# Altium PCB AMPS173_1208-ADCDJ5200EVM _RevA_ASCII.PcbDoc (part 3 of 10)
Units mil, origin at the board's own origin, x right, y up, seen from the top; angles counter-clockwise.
Board outline 10500 x 2750 mil, 14 copper layers (Top Copper, Layer 2 (GND1), Layer 3 (SIG1), Layer 4 (GND2, Layer 5 (PWR1), Layer 6 (GND3), Layer 7 (PWR/SIGNAL2), Layer 8 (PWR/SIGNAL3), Layer 9 (GND4), Layer 10 PWR2), Layer 11 (GND5), Layer 12 (SIG4), Layer 13 (GND6), Bottom Copper), stack 60.6 mil thick; 701 components, 826 nets, 3386 pads, 2128 vias.
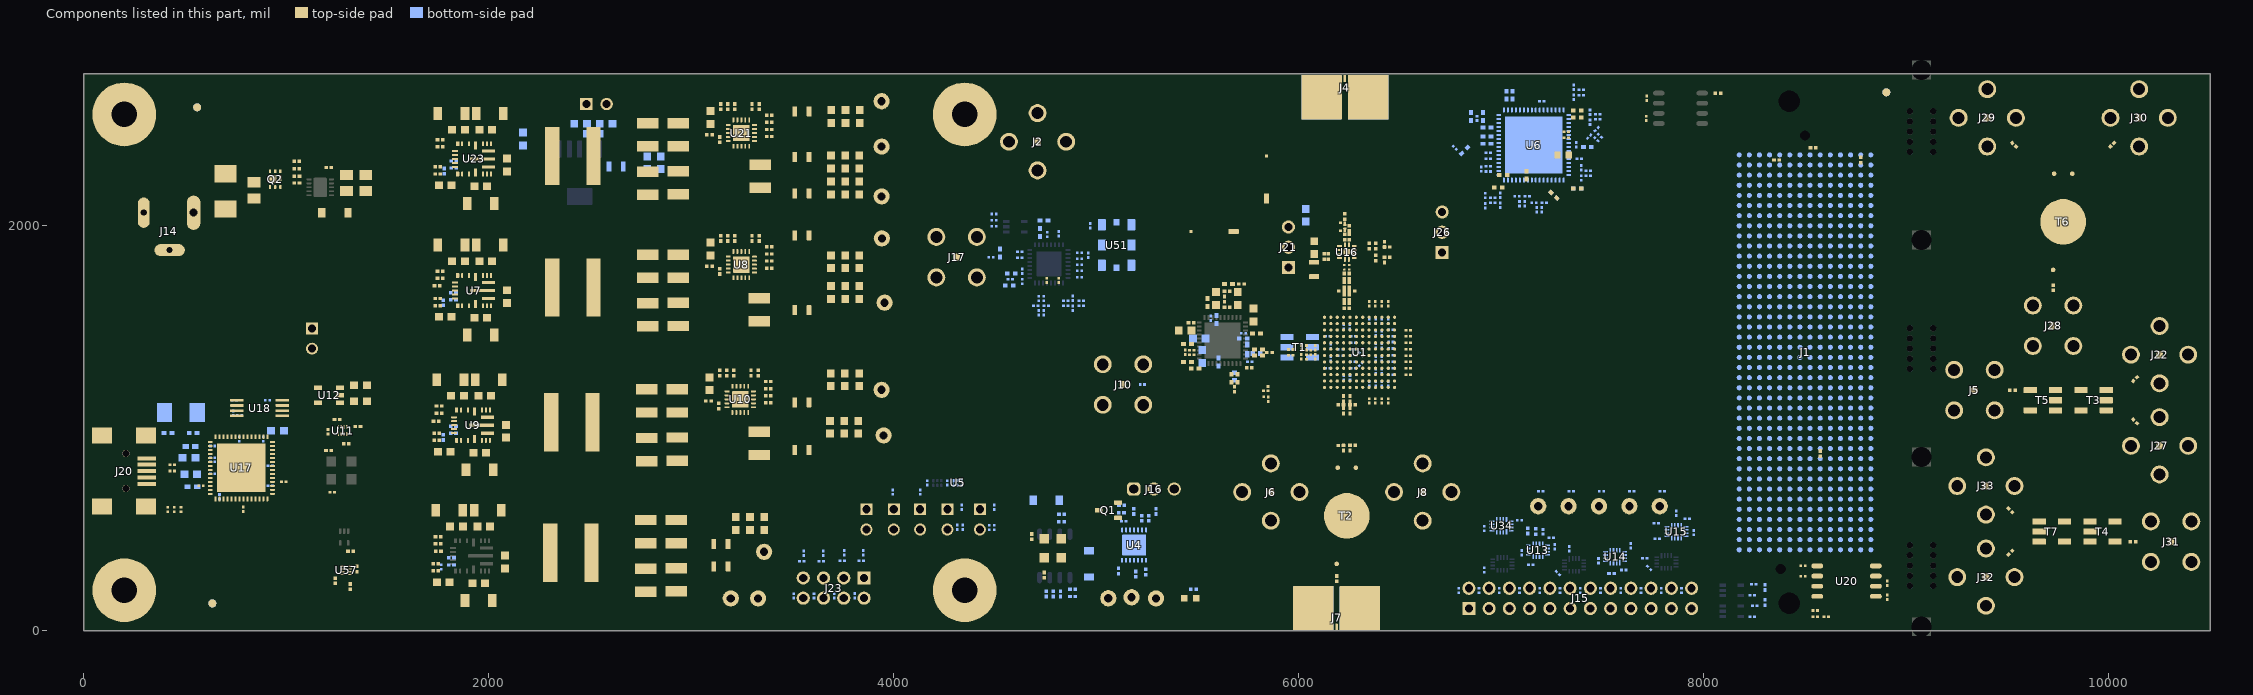
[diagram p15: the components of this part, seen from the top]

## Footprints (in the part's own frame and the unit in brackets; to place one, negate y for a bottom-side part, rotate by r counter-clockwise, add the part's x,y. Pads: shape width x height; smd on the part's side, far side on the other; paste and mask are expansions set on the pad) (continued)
Samtec_ASP-184330-01 [mil] "Terminal Array, 1.27mm, 40x14, SMT"
  round 25 smd paste-25.2: A1(-225,975) A2(-225,925) A3(-225,875) A4(-225,825) A5(-225,775) A6(-225,725) A7(-225,675) A8(-225,625) A9(-225,575) A10(-225,525) A11(-225,475) A12(-225,425) A13(-225,375) A14(-225,325) A15(-225,275) A16(-225,225) A17(-225,175) A18(-225,125) A19(-225,75) A20(-225,25) A21(-225,-25) A22(-225,-75) A23(-225,-125) A24(-225,-175) A25(-225,-225) A26(-225,-275) A27(-225,-325) A28(-225,-375) A29(-225,-425) A30(-225,-475) A31(-225,-525) A32(-225,-575) A33(-225,-625) A34(-225,-675) A35(-225,-725) A36(-225,-775) A37(-225,-825) A38(-225,-875) A39(-225,-925) A40(-225,-975) B1(-175,975) B2(-175,925) B3(-175,875) B4(-175,825) B5(-175,775) B6(-175,725) B7(-175,675) B8(-175,625) B9(-175,575) B10(-175,525) B11(-175,475) B12(-175,425) B13(-175,375) B14(-175,325) B15(-175,275) B16(-175,225) B17(-175,175) B18(-175,125) B19(-175,75) B20(-175,25) B21(-175,-25) B22(-175,-75) B23(-175,-125) B24(-175,-175) B25(-175,-225) B26(-175,-275) B27(-175,-325) B28(-175,-375) B29(-175,-425) B30(-175,-475) B31(-175,-525) B32(-175,-575) B33(-175,-625) B34(-175,-675) B35(-175,-725) B36(-175,-775) B37(-175,-825) B38(-175,-875) B39(-175,-925) B40(-175,-975) C1(-125,975) C2(-125,925) C3(-125,875) C4(-125,825) C5(-125,775) C6(-125,725) C7(-125,675) C8(-125,625) C9(-125,575) C10(-125,525) C11(-125,475) C12(-125,425) C13(-125,375) C14(-125,325) C15(-125,275) C16(-125,225) C17(-125,175) C18(-125,125) C19(-125,75) C20(-125,25) C21(-125,-25) C22(-125,-75) C23(-125,-125) C24(-125,-175) C25(-125,-225) C26(-125,-275) C27(-125,-325) C28(-125,-375) C29(-125,-425) C30(-125,-475) C31(-125,-525) C32(-125,-575) C33(-125,-625) C34(-125,-675) C35(-125,-725) C36(-125,-775) C37(-125,-825) C38(-125,-875) C39(-125,-925) C40(-125,-975) D1(-75,975) D2(-75,925) D3(-75,875) D4(-75,825) D5(-75,775) D6(-75,725) D7(-75,675) D8(-75,625) D9(-75,575) D10(-75,525) D11(-75,475) D12(-75,425) D13(-75,375) D14(-75,325) D15(-75,275) D16(-75,225) D17(-75,175) D18(-75,125) D19(-75,75) D20(-75,25) D21(-75,-25) D22(-75,-75) D23(-75,-125) D24(-75,-175) D25(-75,-225) D26(-75,-275) D27(-75,-325) D28(-75,-375) D29(-75,-425) D30(-75,-475) D31(-75,-525) D32(-75,-575) D33(-75,-625) D34(-75,-675) D35(-75,-725) D36(-75,-775) D37(-75,-825) D38(-75,-875) D39(-75,-925) D40(-75,-975) E1(-25,975) E2(-25,925) E3(-25,875) E4(-25,825) E5(-25,775) E6(-25,725) E7(-25,675) E8(-25,625) E9(-25,575) E10(-25,525) E11(-25,475) E12(-25,425) E13(-25,375) E14(-25,325) E15(-25,275) E16(-25,225) E17(-25,175) E18(-25,125) E19(-25,75) E20(-25,25) E21(-25,-25) E22(-25,-75) E23(-25,-125) E24(-25,-175) E25(-25,-225) E26(-25,-275) E27(-25,-325) E28(-25,-375) E29(-25,-425) E30(-25,-475) E31(-25,-525) E32(-25,-575) E33(-25,-625) E34(-25,-675) E35(-25,-725) E36(-25,-775) E37(-25,-825) E38(-25,-875) E39(-25,-925) E40(-25,-975) F1(25,975) F2(25,925) F3(25,875) F4(25,825) F5(25,775) F6(25,725) F7(25,675) F8(25,625) F9(25,575) F10(25,525) F11(25,475) F12(25,425) F13(25,375) F14(25,325) F15(25,275) F16(25,225) F17(25,175) F18(25,125) F19(25,75) F20(25,25) F21(25,-25) F22(25,-75) F23(25,-125) F24(25,-175) F25(25,-225) F26(25,-275) F27(25,-325) F28(25,-375) F29(25,-425) F30(25,-475) F31(25,-525) F32(25,-575) F33(25,-625) F34(25,-675) F35(25,-725) F36(25,-775) F37(25,-825) F38(25,-875) F39(25,-925) F40(25,-975) G1(75,975) G2(75,925) G3(75,875) G4(75,825) G5(75,775) G6(75,725) G7(75,675) G8(75,625) G9(75,575) G10(75,525) G11(75,475) G12(75,425) G13(75,375) G14(75,325) G15(75,275) G16(75,225) G17(75,175) G18(75,125) G19(75,75) G20(75,25) G21(75,-25) G22(75,-75) G23(75,-125) G24(75,-175) G25(75,-225) G26(75,-275) G27(75,-325) G28(75,-375) G29(75,-425) G30(75,-475) G31(75,-525) G32(75,-575) G33(75,-625) G34(75,-675) G35(75,-725) G36(75,-775) G37(75,-825) G38(75,-875) G39(75,-925) G40(75,-975) H1(125,975) H2(125,925) H3(125,875) H4(125,825) H5(125,775) H6(125,725) H7(125,675) H8(125,625) H9(125,575) H10(125,525) H11(125,475) H12(125,425) H13(125,375) H14(125,325) H15(125,275) H16(125,225) H17(125,175) H18(125,125) H19(125,75) H20(125,25) H21(125,-25) H22(125,-75) H23(125,-125) H24(125,-175) H25(125,-225) H26(125,-275) H27(125,-325) H28(125,-375) H29(125,-425) H30(125,-475) H31(125,-525) H32(125,-575) H33(125,-625) H34(125,-675) H35(125,-725) H36(125,-775) H37(125,-825) H38(125,-875) H39(125,-925) H40(125,-975) J1(175,975) J2(175,925) J3(175,875) J4(175,825) J5(175,775) J6(175,725) J7(175,675) J8(175,625) J9(175,575) J10(175,525) J11(175,475) J12(175,425) J13(175,375) J14(175,325) J15(175,275) J16(175,225) J17(175,175) J18(175,125) J19(175,75) J20(175,25) J21(175,-25) J22(175,-75) J23(175,-125) J24(175,-175) J25(175,-225) J26(175,-275) J27(175,-325) J28(175,-375) J29(175,-425) J30(175,-475) J31(175,-525) J32(175,-575) J33(175,-625) J34(175,-675) J35(175,-725) J36(175,-775) J37(175,-825) J38(175,-875) J39(175,-925) J40(175,-975) K1(225,975) K2(225,925) K3(225,875) K4(225,825) K5(225,775) K6(225,725) K7(225,675) K8(225,625) K9(225,575) K10(225,525) K11(225,475) K12(225,425) K13(225,375) K14(225,325) K15(225,275) K16(225,225) K17(225,175) K18(225,125) K19(225,75) K20(225,25) K21(225,-25) K22(225,-75) K23(225,-125) K24(225,-175) K25(225,-225) K26(225,-275) K27(225,-325) K28(225,-375) K29(225,-425) K30(225,-475) K31(225,-525) K32(225,-575) K33(225,-625) K34(225,-675) K35(225,-725) K36(225,-775) K37(225,-825) K38(225,-875) K39(225,-925) K40(225,-975) L1(275,975) L2(275,925) L3(275,875) L4(275,825) L5(275,775) L6(275,725) L7(275,675) L8(275,625) L9(275,575) L10(275,525) L11(275,475) L12(275,425) L13(275,375) L14(275,325) L15(275,275) L16(275,225) L17(275,175) L18(275,125) L19(275,75) L20(275,25) L21(275,-25) L22(275,-75) L23(275,-125) L24(275,-175) L25(275,-225) L26(275,-275) L27(275,-325) L28(275,-375) L29(275,-425) L30(275,-475) L31(275,-525) L32(275,-575) L33(275,-625) L34(275,-675) L35(275,-725) L36(275,-775) L37(275,-825) L38(275,-875) L39(275,-925) L40(275,-975) M1(325,975) M2(325,925) M3(325,875) M4(325,825) M5(325,775) M6(325,725) M7(325,675) M8(325,625) M9(325,575) M10(325,525) M11(325,475) M12(325,425) M13(325,375) M14(325,325) M15(325,275) M16(325,225) M17(325,175) M18(325,125) M19(325,75) M20(325,25) M21(325,-25) M22(325,-75) M23(325,-125) M24(325,-175) M25(325,-225) M26(325,-275) M27(325,-325) M28(325,-375) M29(325,-425) M30(325,-475) M31(325,-525) M32(325,-575) M33(325,-625) M34(325,-675) M35(325,-725) M36(325,-775) M37(325,-825) M38(325,-875) M39(325,-925) M40(325,-975) Y1(-325,975) Y2(-325,925) Y3(-325,875) Y4(-325,825) Y5(-325,775) Y6(-325,725) Y7(-325,675) Y8(-325,625) Y9(-325,575) Y10(-325,525) Y11(-325,475) Y12(-325,425) Y13(-325,375) Y14(-325,325) Y15(-325,275) Y16(-325,225) Y17(-325,175) Y18(-325,125) Y19(-325,75) Y20(-325,25) Y21(-325,-25) Y22(-325,-75) Y23(-325,-125) Y24(-325,-175) Y25(-325,-225) Y26(-325,-275) Y27(-325,-325) Y28(-325,-375) Y29(-325,-425) Y30(-325,-475) Y31(-325,-525) Y32(-325,-575) Y33(-325,-625) Y34(-325,-675) Y35(-325,-725) Y36(-325,-775) Y37(-325,-825) Y38(-325,-875) Y39(-325,-925) Y40(-325,-975) Z1(-275,975) Z2(-275,925) Z3(-275,875) Z4(-275,825) Z5(-275,775) Z6(-275,725) Z7(-275,675) Z8(-275,625) Z9(-275,575) Z10(-275,525) Z11(-275,475) Z12(-275,425) Z13(-275,375) Z14(-275,325) Z15(-275,275) Z16(-275,225) Z17(-275,175) Z18(-275,125) Z19(-275,75) Z20(-275,25) Z21(-275,-25) Z22(-275,-75) Z23(-275,-125) Z24(-275,-175) Z25(-275,-225) Z26(-275,-275) Z27(-275,-325) Z28(-275,-375) Z29(-275,-425) Z30(-275,-475) Z31(-275,-525) Z32(-275,-575) Z33(-275,-625) Z34(-275,-675) Z35(-275,-725) Z36(-275,-775) Z37(-275,-825) Z38(-275,-875) Z39(-275,-925) Z40(-275,-975)
  round 35 on Bottom Paste: ""(-325,-975) ""(-325,-925) ""(-325,-875) ""(-325,-825) ""(-325,-775) ""(-325,-725) ""(-325,-675) ""(-325,-625) ""(-325,-575) ""(-325,-525) ""(-325,-475) ""(-325,-425) ""(-325,-375) ""(-325,-325) ""(-325,-275) ""(-325,-225) ""(-325,-175) ""(-325,-125) ""(-325,-75) ""(-325,-25) ""(-325,25) ""(-325,75) ""(-325,125) ""(-325,175) ""(-325,225) ""(-325,275) ""(-325,325) ""(-325,375) ""(-325,425) ""(-325,475) ""(-325,525) ""(-325,575) ""(-325,625) ""(-325,675) ""(-325,725) ""(-325,775) ""(-325,825) ""(-325,875) ""(-325,925) ""(-325,975) ""(-275,-975) ""(-275,-925) ""(-275,-875) ""(-275,-825) ""(-275,-775) ""(-275,-725) ""(-275,-675) ""(-275,-625) ""(-275,-575) ""(-275,-525) ""(-275,-475) ""(-275,-425) ""(-275,-375) ""(-275,-325) ""(-275,-275) ""(-275,-225) ""(-275,-175) ""(-275,-125) ""(-275,-75) ""(-275,-25) ""(-275,25) ""(-275,75) ""(-275,125) ""(-275,175) ""(-275,225) ""(-275,275) ""(-275,325) ""(-275,375) ""(-275,425) ""(-275,475) ""(-275,525) ""(-275,575) ""(-275,625) ""(-275,675) ""(-275,725) ""(-275,775) ""(-275,825) ""(-275,875) ""(-275,925) ""(-275,975) ""(-225,-975) ""(-225,-925) ""(-225,-875) ""(-225,-825) ""(-225,-775) ""(-225,-725) ""(-225,-675) ""(-225,-625) ""(-225,-575) ""(-225,-525) ""(-225,-475) ""(-225,-425) ""(-225,-375) ""(-225,-325) ""(-225,-275) ""(-225,-225) ""(-225,-175) ""(-225,-125) ""(-225,-75) ""(-225,-25) ""(-225,25) ""(-225,75) ""(-225,125) ""(-225,175) ""(-225,225) ""(-225,275) ""(-225,325) ""(-225,375) ""(-225,425) ""(-225,475) ""(-225,525) ""(-225,575) ""(-225,625) ""(-225,675) ""(-225,725) ""(-225,775) ""(-225,825) ""(-225,875) ""(-225,925) ""(-225,975) ""(-175,-975) ""(-175,-925) ""(-175,-875) ""(-175,-825) ""(-175,-775) ""(-175,-725) ""(-175,-675) ""(-175,-625) ""(-175,-575) ""(-175,-525) ""(-175,-475) ""(-175,-425) ""(-175,-375) ""(-175,-325) ""(-175,-275) ""(-175,-225) ""(-175,-175) ""(-175,-125) ""(-175,-75) ""(-175,-25) ""(-175,25) ""(-175,75) ""(-175,125) ""(-175,175) ""(-175,225) ""(-175,275) ""(-175,325) ""(-175,375) ""(-175,425) ""(-175,475) ""(-175,525) ""(-175,575) ""(-175,625) ""(-175,675) ""(-175,725) ""(-175,775) ""(-175,825) ""(-175,875) ""(-175,925) ""(-175,975) ""(-125,-975) ""(-125,-925) ""(-125,-875) ""(-125,-825) ""(-125,-775) ""(-125,-725) ""(-125,-675) ""(-125,-625) ""(-125,-575) ""(-125,-525) ""(-125,-475) ""(-125,-425) ""(-125,-375) ""(-125,-325) ""(-125,-275) ""(-125,-225) ""(-125,-175) ""(-125,-125) ""(-125,-75) ""(-125,-25) ""(-125,25) ""(-125,75) ""(-125,125) ""(-125,175) ""(-125,225) ""(-125,275) ""(-125,325) ""(-125,375) ""(-125,425) ""(-125,475) ""(-125,525) ""(-125,575) ""(-125,625) ""(-125,675) ""(-125,725) ""(-125,775) ""(-125,825) ""(-125,875) ""(-125,925) ""(-125,975) ""(-75,-975) ""(-75,-925) ""(-75,-875) ""(-75,-825) ""(-75,-775) ""(-75,-725) ""(-75,-675) ""(-75,-625) ""(-75,-575) ""(-75,-525) ""(-75,-475) ""(-75,-425) ""(-75,-375) ""(-75,-325) ""(-75,-275) ""(-75,-225) ""(-75,-175) ""(-75,-125) ""(-75,-75) ""(-75,-25) ""(-75,25) ""(-75,75) ""(-75,125) ""(-75,175) ""(-75,225) ""(-75,275) ""(-75,325) ""(-75,375) ""(-75,425) ""(-75,475) ""(-75,525) ""(-75,575) ""(-75,625) ""(-75,675) ""(-75,725) ""(-75,775) ""(-75,825) ""(-75,875) ""(-75,925) ""(-75,975) ""(-25,-975) ""(-25,-925) ""(-25,-875) ""(-25,-825) ""(-25,-775) ""(-25,-725) ""(-25,-675) ""(-25,-625) ""(-25,-575) ""(-25,-525) ""(-25,-475) ""(-25,-425) ""(-25,-375) ""(-25,-325) ""(-25,-275) ""(-25,-225) ""(-25,-175) ""(-25,-125) ""(-25,-75) ""(-25,-25) ""(-25,25) ""(-25,75) ""(-25,125) ""(-25,175) ""(-25,225) ""(-25,275) ""(-25,325) ""(-25,375) ""(-25,425) ""(-25,475) ""(-25,525) ""(-25,575) ""(-25,625) ""(-25,675) ""(-25,725) ""(-25,775) ""(-25,825) ""(-25,875) ""(-25,925) ""(-25,975) ""(25,-975) ""(25,-925) ""(25,-875) ""(25,-825) ""(25,-775) ""(25,-725) ""(25,-675) ""(25,-625) ""(25,-575) ""(25,-525) ""(25,-475) ""(25,-425) ""(25,-375) ""(25,-325) ""(25,-275) ""(25,-225) ""(25,-175) ""(25,-125) ""(25,-75) ""(25,-25) ""(25,25) ""(25,75) ""(25,125) ""(25,175) ""(25,225) ""(25,275) ""(25,325) ""(25,375) ""(25,425) ""(25,475) ""(25,525) ""(25,575) ""(25,625) ""(25,675) ""(25,725) ""(25,775) ""(25,825) ""(25,875) ""(25,925) ""(25,975) ""(75,-975) ""(75,-925) ""(75,-875) ""(75,-825) ""(75,-775) ""(75,-725) ""(75,-675) ""(75,-625) ""(75,-575) ""(75,-525) ""(75,-475) ""(75,-425) ""(75,-375) ""(75,-325) ""(75,-275) ""(75,-225) ""(75,-175) ""(75,-125) ""(75,-75) ""(75,-25) ""(75,25) ""(75,75) ""(75,125) ""(75,175) ""(75,225) ""(75,275) ""(75,325) ""(75,375) ""(75,425) ""(75,475) ""(75,525) ""(75,575) ""(75,625) ""(75,675) ""(75,725) ""(75,775) ""(75,825) ""(75,875) ""(75,925) ""(75,975) ""(125,-975) ""(125,-925) ""(125,-875) ""(125,-825) ""(125,-775) ""(125,-725) ""(125,-675) ""(125,-625) ""(125,-575) ""(125,-525) ""(125,-475) ""(125,-425) ""(125,-375) ""(125,-325) ""(125,-275) ""(125,-225) ""(125,-175) ""(125,-125) ""(125,-75) ""(125,-25) ""(125,25) ""(125,75) ""(125,125) ""(125,175) ""(125,225) ""(125,275) ""(125,325) ""(125,375) ""(125,425) ""(125,475) ""(125,525) ""(125,575) ""(125,625) ""(125,675) ""(125,725) ""(125,775) ""(125,825) ""(125,875) ""(125,925) ""(125,975) ""(175,-975) ""(175,-925) ""(175,-875) ""(175,-825) ""(175,-775) ""(175,-725) ""(175,-675) ""(175,-625) ""(175,-575) ""(175,-525) ""(175,-475) ""(175,-425) ""(175,-375) ""(175,-325) ""(175,-275) ""(175,-225) ""(175,-175) ""(175,-125) ""(175,-75) ""(175,-25) ""(175,25) ""(175,75) ""(175,125) ""(175,175) ""(175,225) ""(175,275) ""(175,325) ""(175,375) ""(175,425) ""(175,475) ""(175,525) ""(175,575) ""(175,625) ""(175,675) ""(175,725) ""(175,775) ""(175,825) ""(175,875) ""(175,925) ""(175,975) ""(225,-975) ""(225,-925) ""(225,-875) ""(225,-825) ""(225,-775) ""(225,-725) ""(225,-675) ""(225,-625) ""(225,-575) ""(225,-525) ""(225,-475) ""(225,-425) ""(225,-375) ""(225,-325) ""(225,-275) ""(225,-225) ""(225,-175) ""(225,-125) ""(225,-75) ""(225,-25) ""(225,25) ""(225,75) ""(225,125) ""(225,175) ""(225,225) ""(225,275) ""(225,325) ""(225,375) ""(225,425) ""(225,475) ""(225,525) ""(225,575) ""(225,625) ""(225,675) ""(225,725) ""(225,775) ""(225,825) ""(225,875) ""(225,925) ""(225,975) ""(275,-975) ""(275,-925) ""(275,-875) ""(275,-825) ""(275,-775) ""(275,-725) ""(275,-675) ""(275,-625) ""(275,-575) ""(275,-525) ""(275,-475) ""(275,-425) ""(275,-375) ""(275,-325) ""(275,-275) ""(275,-225) ""(275,-175) ""(275,-125) ""(275,-75) ""(275,-25) ""(275,25) ""(275,75) ""(275,125) ""(275,175) ""(275,225) ""(275,275) ""(275,325) ""(275,375) ""(275,425) ""(275,475) ""(275,525) ""(275,575) ""(275,625) ""(275,675) ""(275,725) ""(275,775) ""(275,825) ""(275,875) ""(275,925) ""(275,975) ""(325,-975) ""(325,-925) ""(325,-875) ""(325,-825) ""(325,-775) ""(325,-725) ""(325,-675) ""(325,-625) ""(325,-575) ""(325,-525) ""(325,-475) ""(325,-425) ""(325,-375) ""(325,-325) ""(325,-275) ""(325,-225) ""(325,-175) ""(325,-125) ""(325,-75) ""(325,-25) ""(325,25) ""(325,75) ""(325,125) ""(325,175) ""(325,225) ""(325,275) ""(325,325) ""(325,375) ""(325,425) ""(325,475) ""(325,525) ""(325,575) ""(325,625) ""(325,675) ""(325,725) ""(325,775) ""(325,825) ""(325,875) ""(325,925) ""(325,975)
  round 0 hole 50 unplated: ""(0,1070.5) ""(120,-1070.5)
  silkscreen extent -405,-1098 389,1133, body extent -389,-1098 389,1133, height 289
SIA0008B [mm] "SIP 8-Leads, Body 5x7mm"
  rrect10% 1x1.4 smd paste-0.5: 1(-1.85,2.54) 2(-1.85,0) 3(-1.85,-2.54) 4(1.85,-2.54) 5(1.85,0) 6(1.85,2.54)
  rrect0% 1x0.6 on Bottom Paste: 1_1(-1.85,2.14) 1_2(-1.85,2.94) 2_1(-1.85,-0.4) 2_2(-1.85,0.4) 3_1(-1.85,-2.14) 3_2(-1.85,-2.94) 4_1(1.85,-2.14) 4_2(1.85,-2.94) 5_1(1.85,-0.4) 5_2(1.85,0.4) 6_1(1.85,2.94) 6_2(1.85,2.14)
  rrect12% 0.8x0.8 smd: 7(0,2.865) 8(0,-2.865)
  silkscreen extent -2.64,-3.63 2.64,3.63, body extent -2.56,-3.56 2.56,3.56, height 1.13
SMB-Bi [mil] "Molded Diode, 2-Leads, Body 5.4x3.6mm, IPC Medium Density, based on OnSemi component dimensions"
  rect 85x107.99 smd: 1(-87.01,0) 2(87.01,0)
  silkscreen extent -125,-79 125,79, body extent -104,-73 104,73, height 89
SOD-123 [mm] "On Semi recommended land pattern"
  rect 0.915x1.22 smd: 1(-1.637,0) 2(1.637,0)
  silkscreen extent -2.74,-1.17 2.03,1.17, body extent -1.93,-0.9 1.93,0.9, height 1.35
SOIC127P800X216-8N [mm] "SOIC, 8-Leads, Body 5.3x5.3mm (max), Pitch 1.27mm, IPC Medium Density"
  oval 1.5x0.6 smd: 1(-3.675,1.905) 2(-3.675,0.635) 3(-3.675,-0.635) 4(-3.675,-1.905) 5(3.675,-1.905) 6(3.675,-0.635) 7(3.675,0.635) 8(3.675,1.905)
  silkscreen extent -4.11,-2.7 2.69,2.7, body extent -4.1,-2.7 4.1,2.7, height 2.17
SOT-23 [mm] "SOT23, 3-Leads, Body 2.9x1.3mm, Pitch 0.95mm, Lead Span 2.5mm, IPC Medium Density"
  rrect50% 1x0.6 smd: 1(-1.2,0.95) 2(-1.2,-0.95) 3(1.2,0)
  silkscreen extent -1.62,-1.5 0.7,1.5, body extent -1.16,-1.45 1.21,1.45, height 1
TI_Stacked_Overlay_Small [mil]
  silkscreen extent -418,-98 418,98
TSSOP-8 [mm] "TSSOP, 8-Leads, Body 3.1x4.5mm (max), Pitch 0.65mm, IPC Medium Density"
  rrect50% 1.7x0.35 smd: 1(-2.85,0.975) 2(-2.85,0.325) 3(-2.85,-0.325) 4(-2.85,-0.975) 5(2.85,-0.975) 6(2.85,-0.325) 7(2.85,0.325) 8(2.85,0.975)
  silkscreen extent -2.97,-1.55 1.6,1.82, body extent -3.2,-1.55 3.2,1.55, height 1.07
TSW-104-07-G-D [mm] "Samtec 100mil, 2x4, 230 mil above insulator"
  rrect6% 1.65x1.65 hole 1.016: 1(-3.81,-1.27)
  round 1.65 hole 1.016: 2(-3.81,1.27) 3(-1.27,-1.27) 4(-1.27,1.27) 5(1.27,-1.27) 6(1.27,1.27) 7(3.81,-1.27) 8(3.81,1.27)
  silkscreen extent -6.11,-2.54 5.08,2.54, body extent -5.08,-2.54 5.08,2.54, height 8.38
TSW-112-07-G-D [mm] "Samtec 100mil, 2x12, 230 mil above insulator"
  rrect6% 1.65x1.65 hole 1.016: 1(-13.97,-1.27)
  round 1.65 hole 1.016: 2(-13.97,1.27) 3(-11.43,-1.27) 4(-11.43,1.27) 5(-8.89,-1.27) 6(-8.89,1.27) 7(-6.35,-1.27) 8(-6.35,1.27) 9(-3.81,-1.27) 10(-3.81,1.27) 11(-1.27,-1.27) 12(-1.27,1.27) 13(1.27,-1.27) 14(1.27,1.27) 15(3.81,-1.27) 16(3.81,1.27) 17(6.35,-1.27) 18(6.35,1.27) 19(8.89,-1.27) 20(8.89,1.27) 21(11.43,-1.27) 22(11.43,1.27) 23(13.97,-1.27) 24(13.97,1.27)
  silkscreen extent -16.26,-2.54 15.24,2.54, body extent -15.24,-2.54 15.24,2.54, height 8.38
VQFN-56 [mm] "VQFN, 56-Leads, Body 8x8mm, Pitch 0.5mm"
  rrect40% 0.6x0.25 smd: 1(-3.9,3.25) 2(-3.9,2.75) 3(-3.9,2.25) 4(-3.9,1.75) 5(-3.9,1.25) 6(-3.9,0.75) 7(-3.9,0.25) 8(-3.9,-0.25) 9(-3.9,-0.75) 10(-3.9,-1.25) 11(-3.9,-1.75) 12(-3.9,-2.25) 13(-3.9,-2.75) 14(-3.9,-3.25) 29(3.9,-3.25) 30(3.9,-2.75) 31(3.9,-2.25) 32(3.9,-1.75) 33(3.9,-1.25) 34(3.9,-0.75) 35(3.9,-0.25) 36(3.9,0.25) 37(3.9,0.75) 38(3.9,1.25) 39(3.9,1.75) 40(3.9,2.25) 41(3.9,2.75) 42(3.9,3.25)
  rrect40% 0.25x0.6 smd: 15(-3.25,-3.9) 16(-2.75,-3.9) 17(-2.25,-3.9) 18(-1.75,-3.9) 19(-1.25,-3.9) 20(-0.75,-3.9) 21(-0.25,-3.9) 22(0.25,-3.9) 23(0.75,-3.9) 24(1.25,-3.9) 25(1.75,-3.9) 26(2.25,-3.9) 27(2.75,-3.9) 28(3.25,-3.9) 43(3.25,3.9) 44(2.75,3.9) 45(2.25,3.9) 46(1.75,3.9) 47(1.25,3.9) 48(0.75,3.9) 49(0.25,3.9) 50(-0.25,3.9) 51(-0.75,3.9) 52(-1.25,3.9) 53(-1.75,3.9) 54(-2.25,3.9) 55(-2.75,3.9) 56(-3.25,3.9)
  rect 6.1x6.1 smd paste-6.1: 57(0,0)
  rect 0.973x0.973 on Top Paste: ""(-2.346,-2.346) ""(-2.346,-1.173) ""(-2.346,0) ""(-2.346,1.173) ""(-2.346,2.346) ""(-1.173,-2.346) ""(-1.173,-1.173) ""(-1.173,0) ""(-1.173,1.173) ""(-1.173,2.346) ""(0,-2.346) ""(0,-1.173) ""(0,0) ""(0,1.173) ""(0,2.346) ""(1.173,-2.346) ""(1.173,-1.173) ""(1.173,0) ""(1.173,1.173) ""(1.173,2.346) ""(2.346,-2.346) ""(2.346,-1.173) ""(2.346,0) ""(2.346,1.173) ""(2.346,2.346)
  body extent -4.04,-4.04 4.04,4.04, height 1
WEEE_Minimum [mil] "WEEElie bin"
  silkscreen extent -95,-172 99,104
WURTH_61300311121 [mm] "Header, 2.54mm, 3x1, TH"
  rrect50% 1.65x1.65 hole 1.15: 1(-2.54,0)
  round 1.65 hole 1.15: 2(0,0) 3(2.54,0)
  body extent -3.81,-1.27 3.81,1.27, height 8.54
XAL8080 [mm] "Coilcraft"
  rect 1.78x7.31 smd: 1(-2.58,0) 2(2.58,0)
  silkscreen extent -4.2,-4.45 4.2,4.45, body extent -4.15,-4.4 4.15,4.4, height 8
XTAL_ABM3 [mm] "Abracon recommended land pattern 12.28.10"
  rect 1.9x2.4 smd: 1(-2.05,0) 2(2.05,0)
  silkscreen extent -2.67,-1.78 2.67,1.78, body extent -2.6,-1.7 2.6,1.7, height 1.3

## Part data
C1 C2 C3 C6 C13 C14 C15 C16 C17 C18 C19 C20 C21 C22 C23 C24 C25 C26 C27 C28 C29 C30 C31 C32 C33 C34 C35 C36 C37 C38 C39 C40 C41 C42 C43 C44 C45 C46 C49 C50 C52 C60 C61 C73 C74 C75 C90 C91 C93 C98 C99 C105 C107 C108 C285 C306 C319 C320 C321 C322 C346 C347 C417 C421 C422 C423 C424 C425 C426 C427 C428 C429 C430 C431 C432 C433 C505 C506 C507 C508: library part CMP-0860981-1, "CAP, CERM, 0.1 µF, 16 V,+/- 10%, X7R, 0201", Cap_Case=0201, Manufacturer="Passive Plus", TempCo=X7R, Tolerance_%=10%, Value2=16V, ValueDisplayed=0.1µF
C4 C5 C324 C333 C415 C416: library part CMP-0009632-3, "CAP, CERM, 100 pF, 25 V, +/- 5%, C0G/NP0, 0201", Cap_Case=0201, Manufacturer=TDK, Supplier Part Number 1=445-4675-1-ND, TempCo=C0G/NP0, Tolerance_%=5%, Value1=Unknown, Value2=25V, ValueDisplayed=100pF
C7 C8 C9 C10 C11 C12 C101 C102 C103 C104 C135 C190 C215 C216 C217 C218 C243 C244 C245: library part CMP-0009220-2, "CAP, CERM, 47 uF, 10 V, +/- 10%, X7R, 1210", Cap_Case=1210, Manufacturer=MuRata, Supplier Part Number 1=490-5312-1-ND, TempCo=X7R, Tolerance_%=10%, Value1=Unknown, Value2=10V, ValueDisplayed=47uF
C47 C53 C54 C55 C56 C57 C58 C315 C316 C326 C331 C332 C334 C335 C339 C341 C344: library part CMP-0064947-2, "CAP, CERM, 1 uF, 6.3 V,+/- 10%, X7R, 0402", Cap_Case=0402, Manufacturer=MuRata, Supplier Part Number 1=490-10024-1-ND, TempCo=X7R, Tolerance_%=10%, Value1=Unknown, Value2=6.3V, ValueDisplayed=1uF
C48 C51 C59 C65 C76 C77 C78 C79 C81 C82 C84 C86 C89 C92 C94 C95 C96 C115 C124 C125 C126 C136 C156 C157 C158 C159 C160 C161 C162 C163 C167 C168 C169 C170 C171 C172 C173 C174 C175 C176 C178 C179 C180 C181 C182 C183 C192 C204 C207 C220 C287 C288 C290 C325 C329 C330 C359 C360 C405: library part CMP-0064970-1, "CAP, CERM, 0.1 uF, 16 V,+/- 10%, X7R, 0201", Cap_Case=0201, Manufacturer=MuRata, Supplier Part Number 1=81-GRM033Z71C104KE4D, TempCo=X7R, Tolerance_%=10%, Value1=Unknown, Value2=16V, ValueDisplayed=0.1uF
C62 C63 C64 C66 C97 C109 C110 C111 C112 C113 C139 C140 C141 C142 C145 C146 C147 C195 C201 C202 C203 C223 C224 C225 C226 C229 C230 C231 C307 C308 C309 C327 C328 C340 C342 C343 C345: library part CMP-0007497-5, "CAP, CERM, 10 uF, 10 V, +/- 20%, X7R, 0603", Cap_Case=0603, Manufacturer=MuRata, Supplier Part Number 1=81-GRM188Z71A106MA3D, TempCo=X7R, Tolerance_%=20%, Value1=Unknown, Value2=10V, ValueDisplayed=10uF
C67 C129 C165 C208: library part CMP-0007424-4, "CAP, CERM, 0.47 uF, 25 V, +/- 10%, X7R, 0603", Cap_Case=0603, Manufacturer=MuRata, Supplier Part Number 1=490-3291-1-ND, TempCo=X7R, Tolerance_%=10%, Value1=Unknown, Value2=25V, ValueDisplayed=0.47uF
C68 C69 C70 C128 C130 C131 C184 C185 C186 C209 C210 C211: library part CMP-0008705-2, "CAP, CERM, 10 uF, 35 V, +/- 10%, X7R, 1206", Cap_Case=1206_180, Manufacturer=TDK, Supplier Part Number 1=445-14799-1-ND, TempCo=X7R, Tolerance_%=10%, Value1="0.002229 ohm", Value2=35V, ValueDisplayed=10uF
C71 C72 C100 C114 C132 C133 C134 C187 C188 C189 C205 C212 C213 C214: library part CMP-0007039-5, "CAP, CERM, 0.1 uF, 25 V, +/- 10%, X7R, 0603", Cap_Case=0603, Manufacturer=TDK, Supplier Part Number 1=445-1316-1-ND, TempCo=X7R, Tolerance_%=10%, Value1=Unknown, Value2=25V, ValueDisplayed=0.1uF
C80: library part CMP-0007008-5, "CAP, CERM, 3.3 uF, 25 V, +/- 10%, X5R, 0603", Cap_Case=0603, Manufacturer=TDK, Supplier Part Number 1=445-14141-1-ND, TempCo=X5R, Tolerance_%=10%, Value1=Unknown, Value2=25V, ValueDisplayed=3.3uF
C83 C85 C116 C137 C193 C221: library part CMP-0064936-4, "CAP, CERM, 4.7 uF, 16 V,+/- 10%, X7R, 0603", Cap_Case=0603, Manufacturer=MuRata, TempCo=X7R, Tolerance_%=10%, Value1=Unknown, Value2=16V, ValueDisplayed=4.7uF
C87 C88: library part CMP-0006247-2, "CAP, CERM, 18 pF, 50 V, +/- 5%, C0G/NP0, 0402", Cap_Case=0402, Manufacturer=TDK, Supplier Part Number 1=445-1238-1-ND, TempCo=C0G/NP0, Tolerance_%=5%, Value1=Unknown, Value2=50V, ValueDisplayed=18pF
C106 C118: library part CMP-2010-01234-1, Manufacturer=Murata, Voltage=50V
C117 C143 C194 C222: library part CMP-0009659-3, "CAP, CERM, 22 pF, 25 V, +/- 5%, C0G/NP0, AEC-Q200 Grade 1, 0201", Cap_Case=0201, Manufacturer=MuRata, Supplier Part Number 1=81-GCM0335C1E220JD3D, TempCo=C0G/NP0, Tolerance_%=5%, Value1=Unknown, Value2=25V, ValueDisplayed=22pF
C119 C120 C121 C122 C123 C127 C138 C148 C149: library part CMP-0860981-1, "CAP, CERM, 0.1 µF, 16 V,+/- 10%, X7R, 0201", Alternate Manufacturer=Murata, Alternate PartNumber=GRM033R60J104KE19D, Cap_Case=0201, Manufacturer="Passive Plus", TempCo=X7R, Tolerance_%=10%, Value2=16V, ValueDisplayed=0.1µF
C144 C164 C199 C200 C227 C228 C310 C311 C312 C313 C314 C317 C318 C323: library part CMP-0009732-1, "CAP, CERM, 0.01 uF, 10 V, +/- 10%, X7R, 0201", Cap_Case=0201, Manufacturer=MuRata, Supplier Part Number 1=490-3194-1-ND, TempCo=X7R, Tolerance_%=10%, Value1=Unknown, Value2=10V, ValueDisplayed=0.01uF
C206: library part CMP-0007365-4, "CAP, CERM, 1 uF, 10 V, +/- 10%, X7R, 0603", Cap_Case=0603, Manufacturer=MuRata, Supplier Part Number 1=490-3899-1-ND, TempCo=X7R, Tolerance_%=10%, Value1="0.011 ohm", Value2=10V, ValueDisplayed=1uF
C235 C236 C237: library part CMP-0007730-2, "CAP, CERM, 1 uF, 50 V, +/- 10%, X7R, 0805", Cap_Case=0805, Manufacturer=Kemet, Supplier Part Number 1=399-7409-1-ND, TempCo=X7R, Tolerance_%=10%, Value1=Unknown, Value2=50V, ValueDisplayed=1uF
C241 C242: library part CMP-0009764-1, "CAP, CERM, 1000 pF, 25 V, +/- 10%, X7R, 0201", Cap_Case=0201, Manufacturer=MuRata, Supplier Part Number 1=490-3184-1-ND, TempCo=X7R, Tolerance_%=10%, Value1=Unknown, Value2=25V, ValueDisplayed=1000pF
C336: library part CMP-0009748-1, "CAP, CERM, 1500 pF, 16 V, +/- 10%, X7R, 0201", Cap_Case=0201, Manufacturer=MuRata, PartNumber=GRM033R71C152KA01D, Supplier Part Number 1=490-5406-1-ND, TempCo=X7R, Tolerance_%=10%, Value1=Unknown, Value2=16V, ValueDisplayed=1500pF
C337: library part CMP-0006264-2, "CAP, CERM, 0.33 uF, 10 V, +/- 10%, X5R, 0402", Cap_Case=0402, Manufacturer=TDK, PartNumber=C1005X5R1A334K050BB, Supplier Part Number 1=445-4987-1-ND, TempCo=X5R, Tolerance_%=10%, Value1=Unknown, Value2=10V, ValueDisplayed=0.33uF
C338: library part CMP-0009647-3, "CAP, CERM, 2200 pF, 25 V, +/- 10%, X7R, AEC-Q200 Grade 1, 0201", Cap_Case=0201_033, Manufacturer=TDK, PartNumber=CGA1A2X7R1E222K030BA, Supplier Part Number 1=445-12093-1-ND, TempCo=X7R, Tolerance_%=10%, Value1="1.26834 ohm", Value2=25V, ValueDisplayed=2200pF
D1: library part CMP-0078131-2, "LED, Red, SMD", Color=Red, Manufacturer=Lite-On, Power_TotalModule=62.5mW, Value1=.0625W, Value2=2V
D2 D3: library part CMP-0002829-3, "LED, Red, SMD", Color=red, Manufacturer=Lite-On, Value1=W, Value2=2V
D4 D5: library part CMP-0076974-2, "Diode, Switching, 100 V, 0.15 A, SOD-123", Manufacturer="Micro Commercial Components", Value1=0.15A, Value2=1.25V
D6: library part CMP-0028547-2, "Diode, Schottky, 30 V, 1 A, SOD-123", Manufacturer="ON Semiconductor", Value1=1A, Value2=0.47V
D7: library part CMP-0006044-3, "Diode, TVS, Bi, 15 V, 24.4 Vc, SMB", Manufacturer="Fairchild Semiconductor", Value1=600W
FB1 FB2 FB3 FB4 FB5 FB6 FB7 FB8 FB9 FB10 FB11: library part CMP-0081829-1, "30 Ohms @ 100MHz 1 Power Line Ferrite Bead 0805 (2012 Metric) 8.5A 4mOhm", Digikey Part Number=490-13266-1-ND, Impedance At Frequency="30O @ 100MHz", Manufacturer=Murata, Mouser Part Number=81-BLM21SN300SN1D, Operating Temperature Range="-55°C to +125°C", Test Frequency=100MHz
FID1 FID2 FID3 FID4 FID5 FID6: library part CMP-0077181-1, "Fiducial mark.  There is nothing to buy or mount.", Manufacturer=N/A
H1 H2 H3 H4: library part CMP-0003617-1, "Machine Screw, Round, #4-40 x 1/4, Nylon, Philips panhead", Manufacturer="B&F Fastener Supply", Supplier Part Number 1=H542-ND
H5 H6 H7 H8: library part CMP-0003917-1, Manufacturer=Keystone, Supplier Part Number 1=36-2204-ND
J1: library part CMP-0055662-1, "Terminal Array, 1.27mm, 40x14, Gold, SMT", Color=Black, Manufacturer=Samtec, Supplier Part Number 1=SAM9173-ND
J2 J5 J6 J8 J10 J17 J22 J27 J28 J29 J30 J31 J32 J33: library part CMP-0055826-1, "Connector, SMA,Vertical, Thru hole w/SMT center pin", Manufacturer="Lighthorse Technologies"
J3: library part CMP-0055333-1, "Header, 2.54mm, 2x1, Tin, TH", Color=Black, Current_A=4A, Manufacturer=Molex, PartNumber=22284023, Supplier Part Number 1=WM50016-02-ND, Voltage_V=250V
J4 J7: library part CMP-0088081-2, "End Launch 2.92mm (K) 40 GHz Jack (Female) Standard Block", Manufacturer="Southwest Microwave"
J9 J11: library part CMP-0077224-1, "Plug, 50 Ohm, Straight, SMT", Color=Gold, Manufacturer=Molex, Voltage_V=335V
J12 J13 J18 J19 J24 J25: library part CMP-0054947-1, "Header, 100mil, 2x1, Gold, TH", Manufacturer="TE Connectivity"
J14: library part CMP-0074940-1, "Power Jack, mini, 2.1mm OD, R/A, TH", Manufacturer=Switchcraft, Supplier Part Number 1=SC1313-ND
J15: library part CMP-0075423-1, "Header, 100mil, 12x2, Gold, TH", Color=Black, Current_A=6.3A, Manufacturer=Samtec, Supplier Part Number 1=SAM1028-12-ND, Voltage_V=550V
J16: library part CMP-0054796-2, "Header, 2.54 mm, 3x1, Gold, TH", Color=Black, Manufacturer="Wurth Elektronik", Supplier Part Number 1=732-5316-ND
J20: library part CMP-0054920-2, "Connector, Receptacle, Mini-USB Type B, R/A, Top Mount SMT", Manufacturer="TE Connectivity", Supplier Part Number 1=A31727CT-ND
J21 J26: library part CMP-0002334-1, "Header, 100mil, 3x1, Gold, TH", Manufacturer="Sullins Connector Solutions", Supplier Part Number 1=S1011E-03-ND
J23: library part CMP-0075408-2, "Header, 100mil, 4x2, Gold, TH", Color=Black, Current_A=6.3A, Manufacturer=Samtec, Supplier Part Number 1=SAM1028-04-ND, Voltage_V=550V
L1 L2 L17 L27: library part CMP-0061060-1, "Inductor, Shielded, Composite, 10 uH, 8.7 A, 0.021 ohm, SMD", Manufacturer=Coilcraft, Supplier Part Number 1=994-XAL8080-103MEB, Value1="0.021 ohm", Value2=8.7A, ValueDisplayed=10uH
L3 L4 L5 L6 L7 L8 L9 L10 L11 L12 L14 L15 L31 L32 L34: library part CMP-0003214-1, "Ferrite Bead, 120 ohm @ 100 MHz, 0.5 A, 0402", Manufacturer="Wurth Elektronik", Supplier Part Number 1=710-74279271, Value1="0.2 ohm", Value2=0.5A, ValueDisplayed="120 ohm"
L13: library part CMP-0088640-1, "Inductor RF Chip Unshielded Wirewound 1.8nH 0.2nH 250MHz 37Q-Factor Non Magnetic 520mA 100mOhm DCR 0201 T/R", Digikey Part Number=490-13820-1-ND, Manufacturer=Murata, Mouser Part Number=81-LQW03AW1N8C00D, Operating Temperature Range="-55°C to +125°C", Self Resonant Frequency=19GHz, Test Frequency=250MHz, Tolerance_%=0.2nH
L33 L35: library part CMP-0058614-1, "Inductor, Multilayer, Air Core, 18 nH, 0.3 A, 0.36 ohm, SMD", Manufacturer=MuRata, Supplier Part Number 1=490-2626-1-ND, Value1="0.36 ohm", Value2=0.3A, ValueDisplayed=18nH
LBL1: library part CMP-0003625-1, "Thermal Transfer Printable Labels, 0.650\" W x 0.200\" H - 10,000 per roll", Manufacturer=Brady, Supplier Part Number 1=97C5133
Logo1: library part CMP-0074838-1, "Texas Instrument Corporate Signature"
Logo2: library part CMP-0074844-1
Logo3: library part CMP-0074847-1, "FCC_disclaimer"
Logo4: library part CMP-0074769-1
Q1: library part CMP-0000386-2, "Transistor, NPN, 40 V, 0.2 A, SOT-23", Manufacturer="Fairchild Semiconductor", Supplier Part Number 1=MMBT3904FSCT-ND, Value1="0.2 A", Value2=300
Q2: library part CMP-0000207-1, "MOSFET, N-CH, 20 V, 10 A, DQK0006C (WSON-6)", Alternate Manufacturer=None, Manufacturer="Texas Instruments", Supplier Part Number 1=CSD15571Q2-ND, Value1=19, Value2="2.5 nC"
R1 R2 R193: library part CMP-0027289-3, "RES, 49.9, 1%, 0.05 W, AEC-Q200 Grade 1, 0201", Manufacturer=Panasonic, Power_W=50mW, Supplier Part Number 1=P49.9ABCT-ND, TempCo="200 ppm/C", Tolerance_%=1%, Value2=0.05W, Value_Code=49R9, ValueDisplayed=49.9
R3 R4: library part CMP-0027262-3, "RES, 10.0 k, 1%, 0.05 W, 0201", Manufacturer=Vishay-Dale, Power_W=50mW, Supplier Part Number 1=541-10.0KAABCT-ND, TempCo="100 ppm/C", Tolerance_%=1%, Value2=0.05W, Value_Code=10k0, ValueDisplayed=10.0k
R5: library part CMP-0023050-5, "RES, 35.7 k, 1%, 0.1 W, 0603", Manufacturer=Yageo, Power_W=100mW, Supplier Part Number 1=311-35.7KHRCT-ND, TempCo="100 ppm/C", Tolerance_%=1%, Value2=0.1W, Value_Code=35k7, ValueDisplayed=35.7k
R6: library part CMP-0065361-1, "RES, 0, 5%, .05 W, AEC-Q200 Grade 0, 0201", Manufacturer=Panasonic, Power_W=50mW, Supplier Part Number 1=P15979CT-ND, TempCo=ppm/C, Tolerance_%=5%, Value2=.05W, Value_Code=0000, ValueDisplayed=0
R7 R194 R195 R196 R197: library part CMP-0027011-4, "RES, 0, 5%, 0.05 W, AEC-Q200 Grade 1, 0201", Manufacturer=Panasonic, Power_W=50mW, Supplier Part Number 1=P0.0AGCT-ND, TempCo="600 ppm/C", Tolerance_%=5%, Value2=0.05W, Value_Code=0000, ValueDisplayed=0
R11 R15 R22 R23 R181 R182 R186 R187: library part CMP-0750119-1, "RES, 8.66, 1%, 0.05 W, 0201", Manufacturer=Yageo, Power_W=50mW, TempCo="350 ppm/C", Tolerance_%=1%, Value2=0.05W, Value_Code=8R66, ValueDisplayed=8.66
R12 R13 R184 R189: library part CMP-0027355-2, "RES, 140, 1%, 0.05 W, 0201", Manufacturer="Yageo America", Power_W=50mW, Supplier Part Number 1=YAG2406CT-ND, TempCo="200 ppm/C", Tolerance_%=1%, Value2=0.05W, Value_Code=140R, ValueDisplayed=140
R20 R21 R32 R37 R38 R39 R40 R41 R42 R44 R49 R51 R53 R54 R59 R62 R63 R72 R76 R79 R85 R88 R98 R100 R101 R102 R103 R105 R106 R110 R111 R112 R118 R120 R122 R123 R124 R125 R126 R135 R137 R139 R140 R141 R142 R143 R148 R149 R150 R151 R165 R171 R172 R174 R215 R217 R218 R220 R226 R227 R240 R242 R245 R246 R247 R804 R807 R808 R852: library part CMP-0027008-4, "RES, 0, 5%, 0.05 W, 0201", Manufacturer=Vishay-Dale, Power_W=50mW, Supplier Part Number 1=72M6743, TempCo=ppm/C, Tolerance_%=5%, Value2=0.05W, Value_Code=0000, ValueDisplayed=0
R24 R25 R26 R31 R43 R75 R77 R80 R81 R166 R167 R168 R169 R175 R255 R262 R750 R801 R805 R851: library part CMP-0027945-1, "RES, 10.0 k, 1%, 0.05 W, 0201", Manufacturer="Yageo America", Power_W=50mW, Supplier Part Number 1=603-RC0201FR-7D10KL, TempCo="200 ppm/C", Tolerance_%=1%, Value2=0.05W, Value_Code=10k0, ValueDisplayed=10.0k
R27 R33 R34 R36 R60 R61 R66 R71 R82 R83 R87 R91 R104 R107 R109 R178 R207 R219 R239 R241 R251 R265 R278 R451: library part CMP-0028070-1, "RES, 100, 1%, 0.05 W, 0201", Manufacturer="Yageo America", Power_W=50mW, Supplier Part Number 1=603-RC0201FS-7D100RL, TempCo="200 ppm/C", Tolerance_%=1%, Value2=0.05W, Value_Code=100R, ValueDisplayed=100
R28 R69 R84 R89 R108 R147: library part CMP-0027723-1, "RES, 47.0 k, 1%, 0.05 W, 0201", Manufacturer="Yageo America", Power_W=50mW, Supplier Part Number 1=311-47KMCT-ND, TempCo="200 ppm/C", Tolerance_%=1%, Value2=0.05W, Value_Code=47k0, ValueDisplayed=47.0k
R29: library part CMP-0027865-1, "RES, 750, 1%, 0.05 W, 0201", Manufacturer="Yageo America", Power_W=50mW, Supplier Part Number 1=YAG2794CT-ND, TempCo="200 ppm/C", Tolerance_%=1%, Value2=0.05W, Value_Code=750R, ValueDisplayed=750
R30 R248: library part CMP-0026703-1, "RES, 49.9, 1%, 0.1 W, AEC-Q200 Grade 0, 0402", Manufacturer=Panasonic, Power_W=100mW, Supplier Part Number 1=P49.9LCT-ND, TempCo="100 ppm/C", Tolerance_%=1%, Value2=0.1W, Value_Code=49R9, ValueDisplayed=49.9
R35 R67 R68 R90 R152 R158 R159 R161 R279: library part CMP-0028084-1, "RES, 1.00 k, 1%, 0.05 W, 0201", Manufacturer="Yageo America", Power_W=50mW, Supplier Part Number 1=603-RC0201FS-7D1KL, TempCo="200 ppm/C", Tolerance_%=1%, Value2=0.05W, Value_Code=1k00, ValueDisplayed=1.00k
R45 R46 R47 R48 R50 R52 R55 R56 R64 R65 R238 R256: library part CMP-0027984-1, "RES, 240, 1%, 0.05 W, 0201", Manufacturer="Yageo America", Power_W=50mW, Supplier Part Number 1=603-RC0201FR-7D240RL, TempCo="200 ppm/C", Tolerance_%=1%, Value2=0.05W, Value_Code=240R, ValueDisplayed=240
R57 R58 R359 R360: library part CMP-0027327-2, "RES, 120, 1%, 0.05 W, 0201", Manufacturer="Yageo America", Power_W=50mW, Supplier Part Number 1=311-120MCT-ND, TempCo="200 ppm/C", Tolerance_%=1%, Value2=0.05W, Value_Code=120R, ValueDisplayed=120
R70 R86 R305: library part CMP-0027540-1, "RES, 27.0, 1%, 0.05 W, 0201", Manufacturer="Yageo America", PartNumber=RC0201FR-0727RL, Power_W=50mW, Supplier Part Number 1=YAG2554CT-ND, TempCo="200 ppm/C", Tolerance_%=1%, Value2=0.05W, Value_Code=27R0, ValueDisplayed=27.0
R73 R74 R78: library part CMP-0027945-1, "RES, 10.0 k, 1%, 0.05 W, 0201", Manufacturer="Yageo America", PartNumber=RC0201FR-7D10KL, Power_W=50mW, Supplier Part Number 1=603-RC0201FR-7D10KL, TempCo="200 ppm/C", Tolerance_%=1%, Value2=0.05W, Value_Code=10k0, ValueDisplayed=10.0k
R92 R95 R99 R113 R117 R119 R130 R134 R136 R146 R230 R231 R280 R888 R950: library part CMP-0028107-1, "RES, 4.99 k, 1%, 0.05 W, 0201", Manufacturer="Yageo America", Power_W=50mW, Supplier Part Number 1=603-RC0201FS-7D4K99L, TempCo="200 ppm/C", Tolerance_%=1%, Value2=0.05W, Value_Code=4k99, ValueDisplayed=4.99k
R93 R114 R131 R228: library part CMP-0027685-1, "RES, 3.00, 1%, 0.05 W, 0201", Manufacturer="Yageo America", Power_W=50mW, Supplier Part Number 1=RC0201FR-073RL-ND, TempCo="350 ppm/C", Tolerance_%=1%, Value2=0.05W, Value_Code=3R00, ValueDisplayed=3.00
R94 R116 R132: library part CMP-0028069-1, "RES, 100 k, 1%, 0.05 W, 0201", Manufacturer="Yageo America", PartNumber=RC0201FS-7D100KL, Power_W=50mW, Supplier Part Number 1=603-RC0201FS-7D100KL, TempCo="200 ppm/C", Tolerance_%=1%, Value2=0.05W, Value_Code=100k
R96 R115 R133 R229: library part CMP-0028027-1, "RES, 49.9 k, 1%, 0.05 W, 0201", Manufacturer="Yageo America", Power_W=50mW, Supplier Part Number 1=603-RC0201FR-7D49K9L, TempCo="200 ppm/C", Tolerance_%=1%, Value2=0.05W, Value_Code=49k9, ValueDisplayed=49.9k
R97: library part CMP-0027952-1, "RES, 124 k, 1%, 0.05 W, 0201", Manufacturer="Yageo America", Power_W=50mW, Supplier Part Number 1=603-RC0201FR-7D124KL, TempCo="200 ppm/C", Tolerance_%=1%, Value2=0.05W, Value_Code=124k
R121: library part CMP-0027692-1, "RES, 41.2 k, 1%, 0.05 W, 0201", Manufacturer="Yageo America", Power_W=50mW, Supplier Part Number 1=YAG2662CT-ND, TempCo="200 ppm/C", Tolerance_%=1%, Value2=0.05W, Value_Code=41k2, ValueDisplayed=41.2k
R127 R128 R129 R233: library part CMP-0027615-1, "RES, 33.0, 1%, 0.05 W, 0201", Manufacturer="Yageo America", Power_W=50mW, Supplier Part Number 1=311-33.0MCT-ND, TempCo="200 ppm/C", Tolerance_%=1%, Value2=0.05W, Value_Code=33R0, ValueDisplayed=33.0
R138: library part CMP-0027418-1, "RES, 19.1 k, 1%, 0.05 W, 0201", Manufacturer="Yageo America", Power_W=50mW, Supplier Part Number 1=YAG2464CT-ND, TempCo="200 ppm/C", Tolerance_%=1%, Value2=0.05W, Value_Code=19k1, ValueDisplayed=19.1k
R144: library part CMP-0027974-1, "RES, 1.00 M, 1%, 0.05 W, 0201", Manufacturer="Yageo America", Power_W=50mW, Supplier Part Number 1=603-RC0201FR-7D1ML, TempCo="200 ppm/C", Tolerance_%=1%, Value2=0.05W, Value_Code=1M00, ValueDisplayed=1.00M
R145: library part CMP-0028019-1, "RES, 45.3 k, 1%, 0.05 W, 0201", Manufacturer="Yageo America", Power_W=50mW, Supplier Part Number 1=603-RC0201FR-7D45K3L, TempCo="200 ppm/C", Tolerance_%=1%, Value2=0.05W, Value_Code=45k3, ValueDisplayed=45.3k
R153 R155 R163: library part CMP-0027944-1, "RES, 100, 1%, 0.05 W, 0201", Manufacturer="Yageo America", Power_W=50mW, Supplier Part Number 1=603-RC0201FR-7D100RL, TempCo="200 ppm/C", Tolerance_%=1%, Value2=0.05W, Value_Code=100R, ValueDisplayed=100
R156 R157: library part CMP-0027946-1, "RES, 10.0, 1%, 0.05 W, 0201", Manufacturer="Yageo America", Power_W=50mW, Supplier Part Number 1=603-RC0201FR-7D10RL, TempCo="350 ppm/C", Tolerance_%=1%, Value2=0.05W, Value_Code=10R0, ValueDisplayed=10.0
R160 R162: library part CMP-0027954-1, "RES, 12.0 k, 1%, 0.05 W, 0201", Manufacturer="Yageo America", Power_W=50mW, Supplier Part Number 1=603-RC0201FR-7D12KL, TempCo="200 ppm/C", Tolerance_%=1%, Value2=0.05W, Value_Code=12k0, ValueDisplayed=12.0k
R164 R176: library part CMP-0027059-1, "RES, 1.0 M, 5%, 0.05 W, 0201", Manufacturer="Yageo America", Power_W=50mW, Supplier Part Number 1=311-1MNCT-ND, TempCo="200 ppm/C", Tolerance_%=5%, Value2=0.05W, Value_Code=1M00, ValueDisplayed=1.0M
R170: library part CMP-0027995-1, "RES, 2.20 k, 1%, 0.05 W, 0201", Manufacturer="Yageo America", Power_W=50mW, Supplier Part Number 1=603-RC0201FR-7D2K2L, TempCo="200 ppm/C", Tolerance_%=1%, Value2=0.05W, Value_Code=2k20, ValueDisplayed=2.20k
R177: library part CMP-0028120-1, "RES, 8.06 k, 1%, 0.05 W, 0201", Manufacturer="Yageo America", Power_W=50mW, Supplier Part Number 1=603-RC0201FS-7D8K06L, TempCo="200 ppm/C", Tolerance_%=1%, Value2=0.05W, Value_Code=8k06, ValueDisplayed=8.06k
R179: library part CMP-0023153-5, "RES, 4.70 k, 1%, 0.1 W, 0603", Manufacturer=Yageo, Power_W=100mW, Supplier Part Number 1=311-4.70KHRCT-ND, TempCo="100 ppm/C", Tolerance_%=1%, Value2=0.1W, Value_Code=4k70, ValueDisplayed=4.70k
R180 R185: library part CMP-0088349-1, "RES SMD 5.1 OHM 5% 1/20W 0201", Digikey Part Number=P123350CT-ND, Manufacturer=Panasonic, Mouser Part Number=667-ERJ-1GNJ5R1C, Operating Temperature Range="-55°C to +125°C", Power_W=50mW, TempCo=-100/600ppm/°C, Tolerance_%=5%
R183 R188: library part CMP-0027021-3, "RES, 10, 5%, 0.05 W, 0201", Manufacturer="Yageo America", Power_W=50mW, Supplier Part Number 1=311-10NCT-ND, TempCo="350 ppm/C", Tolerance_%=5%, Value2=0.05W, Value_Code=10R0, ValueDisplayed=10
R198: library part CMP-0023030-5, "RES, 32.4 k, 1%, 0.1 W, 0603", Manufacturer=Yageo, Power_W=100mW, Supplier Part Number 1=311-32.4KHRCT-ND, TempCo="100 ppm/C", Tolerance_%=1%, Value2=0.1W, Value_Code=32k4, ValueDisplayed=32.4k
R199: library part CMP-0025886-5, "RES, 10 k, 5%, 0.1 W, 0603", Manufacturer=Yageo, Power_W=100mW, Supplier Part Number 1=311-10KGRCT-ND, TempCo="100 ppm/C", Tolerance_%=5%, Value2=0.1W, Value_Code=10k0, ValueDisplayed=10k
R216: library part CMP-0027433-1, "RES, 1.33 k, 1%, 0.05 W, 0201", Manufacturer="Yageo America", Power_W=50mW, Supplier Part Number 1=YAG2479CT-ND, TempCo="200 ppm/C", Tolerance_%=1%, Value2=0.05W, Value_Code=1k33, ValueDisplayed=1.33k
R232: library part CMP-0027730-1, "RES, 499 k, 1%, 0.05 W, 0201", Manufacturer="Yageo America", Power_W=50mW, Supplier Part Number 1=YAG2699CT-ND, TempCo="200 ppm/C", Tolerance_%=1%, Value2=0.05W, Value_Code=499k
R243 R244 R249 R250: library part CMP-0027379-2, "RES, 160, 1%, 0.05 W, 0201", Manufacturer="Yageo America", Power_W=50mW, Supplier Part Number 1=YAG2427CT-ND, TempCo="200 ppm/C", Tolerance_%=1%, Value2=0.05W, Value_Code=160R, ValueDisplayed=160
R252 R253 R258 R259: library part CMP-0026404-2, "RES, 49.9, 1%, 0.063 W, AEC-Q200 Grade 0, 0402", Manufacturer=Vishay-Dale, Power_W=63mW, Supplier Part Number 1=541-49.9LCT-ND, TempCo="100 ppm/C", Tolerance_%=1%, Value2=0.063W, Value_Code=49R9, ValueDisplayed=49.9
R254: library part CMP-0028028-1, "RES, 49.9, 1%, 0.05 W, 0201", Manufacturer="Yageo America", Power_W=50mW, Supplier Part Number 1=603-RC0201FR-7D49R9L, TempCo="200 ppm/C", Tolerance_%=1%, Value2=0.05W, Value_Code=49R9, ValueDisplayed=49.9
R263: library part CMP-0027498-1, "RES, 22.1, 1%, 0.05 W, 0201", Manufacturer="Yageo America", PartNumber=RC0201FR-0722R1L, Power_W=50mW, Supplier Part Number 1=YAG2516CT-ND, TempCo="200 ppm/C", Tolerance_%=1%, Value2=0.05W, Value_Code=22R1, ValueDisplayed=22.1
R264: library part CMP-0027375-2, "RES, 15.4, 1%, 0.05 W, 0201", Manufacturer="Yageo America", PartNumber=RC0201FR-0715R4L, Power_W=50mW, Supplier Part Number 1=YAG2424CT-ND, TempCo="200 ppm/C", Tolerance_%=1%, Value2=0.05W, Value_Code=15R4, ValueDisplayed=15.4
R277: library part CMP-0028024-1, "RES, 47.0 k, 1%, 0.05 W, 0201", Manufacturer="Yageo America", Power_W=50mW, Supplier Part Number 1=603-RC0201FR-7D47KL, TempCo="200 ppm/C", Tolerance_%=1%, Value2=0.05W, Value_Code=47k0, ValueDisplayed=47.0k
T1: library part CMP-0030469-2, "RF Transformer, 50 Ohm, SMT", Manufacturer=Minicircuits
T2 T6: library part CMP-0090705-1, "10 MHz to 20 GHz 1:2 Balun, Surface Mount", Frequency_Fixed=0.01-20GHz, Manufacturer="Marki Microwave", Operating Temperature Range="-55°C to +100°C"
T3 T4 T5 T7: library part CMP-0087865-1, "RF Transformer Surface Mount 50? 4.5 to 3000 MHz", Manufacturer=Mini-Circuits
TP1 TP2 TP3 TP4 TP5 TP7 TP9 TP10 TP11 TP16 TP20 TP21: library part CMP-0055137-1, "Test Point, Miniature, Red, TH", Color=Red, Manufacturer=Keystone, Supplier Part Number 1=36-5000-ND
TP6: library part CMP-0055138-1, "Test Point, Miniature, Black, TH", Color=Black, Manufacturer=Keystone, Supplier Part Number 1=36-5001-ND
TP8 TP12 TP13 TP14 TP15: library part CMP-0055139-1, "Test Point, Miniature, White, TH", Color=White, Manufacturer=Keystone, Supplier Part Number 1=36-5002-ND
U1: library part CMP-0065050-3, "6.4-GSPS Single Channel or 3.2-GSPS Dual Channel 12-bit Analog-to-Digital Converter (ADC) Family, AAV0144A (FCBGA-144)", Alternate Manufacturer="Texas Instruments", Alternate PartNumber=ADC12DJ3200AAVT
U4: library part CMP-0073387-3, "+/-2degC Dual Remote and Local Temperature Sensor with TruTherm Technology and SMBus Interface, NHL0014B (WSON-14)", Manufacturer="Texas Instruments", Operating Temperature Range="-40 to 140 C", Rating=Catalog
U5: library part CMP-0051432-4, "Low-Power Single Bus Buffer Gate with 3-State Output, DRY0006A (USON-6)", F @ Nom Voltage(Max)(Mhz)=100, Generic Part Number=SN74AUP1G126, ICC @ Nom Voltage(Max)(mA)=0.0009, Manufacturer="Texas Instruments", Operating Temperature Range="-40 to 85 C", Operating Temperature Range(C)="-40 to 85", Rating=Catalog, tpd @ Nom Voltage(Max)(ns)=29,18.7,12.5,10.1,7.2,6, Voltage(Nom)(V)=0.8,1.2,1.5,1.8,2.5,3.3
U6: library part CMP-0084462-1, "Ultra Low Jitter Synthesizer and Jitter Cleaner, NKD0064A (WQFN-64)", Alternate Manufacturer="Texas Instruments", Alternate PartNumber=LMK04828BISQX/NOPB, Operating Temperature Range="-40 to 85 C", Rating=Catalog
U7 U9 U23: library part CMP-0013906-5, "3.5A, 36V Synchronous, 400kHz, Step-Down Converter, RNL0022A (VQFN-HR-22)", Alternate Manufacturer="Texas Instruments", Alternate PartNumber=LMS3635MQRNLTQ1, Operating Temprature Range="-40 to 150 C", Rating=Automotive
U8 U10 U21: library part CMP-0073871-3, "High-Current (3 A), High-Accuracy (1%), Low-Noise (4.4 uVRMS), LDO Voltage Regulator, RGR0020A (VQFN-20)", Alternate Manufacturer="Texas Instruments", Alternate PartNumber=TPS7A8400RGRT
U11 U57: library part CMP-0051481-3, "Single Positive-Edge-Triggered D-Type Flip-Flop With Clear and Preset, DQE0008A (X2SON-8)", F @ Nom Voltage(Max)(Mhz)=150, Generic Part Number=SN74LVC1G74, ICC @ Nom Voltage(Max)(mA)=0.01, Manufacturer="Texas Instruments", Operating Temperature Range="-40 to 125 C", Operating Temperature Range(C)="-40 to 125", Rating=Catalog, tpd @ Nom Voltage(Max)(ns)=13.4,7.1,5.9,4.1, Voltage(Nom)(V)=1.8,2.5,3.3,5
U12: library part CMP-0035537-1, "Single Output LDO, 150 mA, Fixed 3.3 V Output, 2.5 to 24 V Input, with Ultra-Low IQ, 5-pin SOT-23 (DBV), -40 to 85 degC, Green (RoHS & no Sb/Br)", Manufacturer="Texas Instruments"
U13 U14 U15 U34: library part CMP-0066452-2, "4-Bit Dual-Supply Bus Transceiver With Configurable Voltage-Level Shifting and 3-State Outputs, RSV0016A (UQFN-16)", Alternate Manufacturer="Texas Instruments", Operating Temperature Range="-40 to 85 C", Rating=Catalog
U16: "LMH81XX", Alternate Manufacturer="Texas Instruments"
